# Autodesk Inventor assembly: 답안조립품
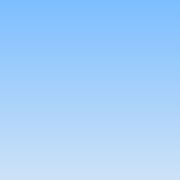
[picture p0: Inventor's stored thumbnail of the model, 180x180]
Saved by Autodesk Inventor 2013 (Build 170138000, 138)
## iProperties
Created: 2015-03
Part Number: 답안조립품
Document SubType Name: Assembly
Designer: ST5
Author: ST5
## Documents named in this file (1)
- C:\Users\ST5\Desktop\450305V1010\답안조립품.iam
